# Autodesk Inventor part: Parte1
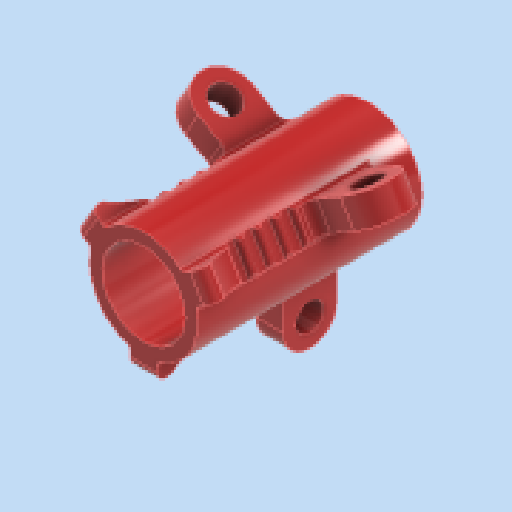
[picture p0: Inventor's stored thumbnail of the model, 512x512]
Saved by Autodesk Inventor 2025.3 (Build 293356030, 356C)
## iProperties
Created: 2026-05
Part Number: Parte1
Material: Generico
Document SubType Name: Modeling
Designer: Ryzen5700u
Density: 1 g/cm^3
Appearance: Rosso
Author: Ryzen5700u
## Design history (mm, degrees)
sketch "Schizzo1"
  geometry: C1 r 6 at (0, 0); C2 r 4.6 at (0, 0); 1 further point
  constraints: 2 centre point, 1 coincident
  dimensions: "d0" = 12 diameter of C1; "d1" = 1.4 radial gap between concentric circles of C1 C2
extrude "Estrusione1" new body sketch "Schizzo1" distance "d2" = 25; taper "d3" = 0 deg
node "Piano di lavoro1"
sketch "Schizzo2"
  geometry: L1 (-6, 0)-(-6, 25) reference; L2 (-6, 11)-(-13, 11); L3 (-13, 11)-(-13, 5); L4 (-13, 5)-(-6, 5); L5 (-6, 5)-(-6, 11); L6 (-4.6, 25)-(4.6, 25) reference; L7 (-13, 8)-(-6, 8); L8 (-6, 11)-(-5, 11); L9 (-5, 11)-(-5, 5); L10 (-5, 5)-(-6, 5); L11 (-6, 5)-(-6, 11); L12 (6, 25)-(-6, 25) reference; L13 (-6, 25)-(-9, 25); L14 (-9, 25)-(-9, 11); L15 (6, 25)-(-6, 25) reference; L16 (6, 0)-(-6, 0) reference; L17 (-6, 25)-(-5, 25); L18 (-5, 25)-(-5, 11); L19 (-5, 11)-(-6, 11); L20 (-6, 11)-(-6, 25); C1 r 1.6 at (-10, 8); A1 r 9.667 centre (-15.667, 18) between (-9, 11) and (-9, 25); 6 further points
  constraints: 30 end point, 6 parallel, 4 horizontal, 4 perpendicular, 3 point on line, 2 centre point, 2 midpoint, 2 point on circle, 1 tangent
  dimensions: "d5" = 7 distance of L4.end L3.end; "d6" = 6 distance of L3.end L2.end; "d7" = 14 distance between parallel lines of L6 L2; "d11" = 3.2 diameter of C1; "d15" = 1 distance of L4.end L9.end; "d19" = 3 distance from line of L3 C1.centre; "d20" = 3 distance of L1.end L13.end
extrude "Estrusione2" join sketch "Schizzo2" stored distance "d9" = 3; taper "d10" = 0 deg
pattern_circular "Serie circolare1" dims angle "d13" = 360 deg
fillet "Raccordo1" dims "d16" = 3
fillet "Raccordo2" dims "d17" = 1
fillet "Raccordo3" dims "d18" = 0.5
fillet "Raccordo4" dims "d21" = 1
fillet "Raccordo5" dims "d22" = 1
sketch "Schizzo3"
  geometry: L1 (3.071, -6)-(0, -6) reference; L2 (3.071, 0)-(3.071, -6) reference; L3 (0, 0)-(3.071, 0) reference; L4 (0, -6)-(0, 0) reference; L5 (-0.311, 7)-(-0.311, -14) reference; L6 (3.382, -14)-(3.382, 7) reference; L7 (-0.311, 0)-(3.382, 0); L8 (3.382, 0)-(3.382, -1); L9 (3.382, -1)-(-0.311, -1); L10 (-0.311, -1)-(-0.311, 0); 5 further points
  constraints: 8 end point, 2 parallel, 2 point on line, 1 horizontal, 1 perpendicular
  dimensions: "d24" = 1 distance of L7.end L8.end
extrude "Estrusione3" cut sketch "Schizzo3" distance "d25" = 1; taper "d26" = 0 deg; dims "d33" = 0.5, "d34" = 0
pattern_linear "Serie rettangolare1" dims "d29" = 2, "d37" = 2
pattern_circular "Serie circolare2" dims "d31" = 360 deg
fillet "Raccordo6" dims "d38" = 0.5
fillet "Raccordo7" dims "d39" = 0.5
pattern_circular "Serie circolare3" dims angle "d41" = 360 deg
node "Solido1"
node "Linea chiusa proiettata1"
node "Linea chiusa proiettata2"
other parameters: "d4" = -25
